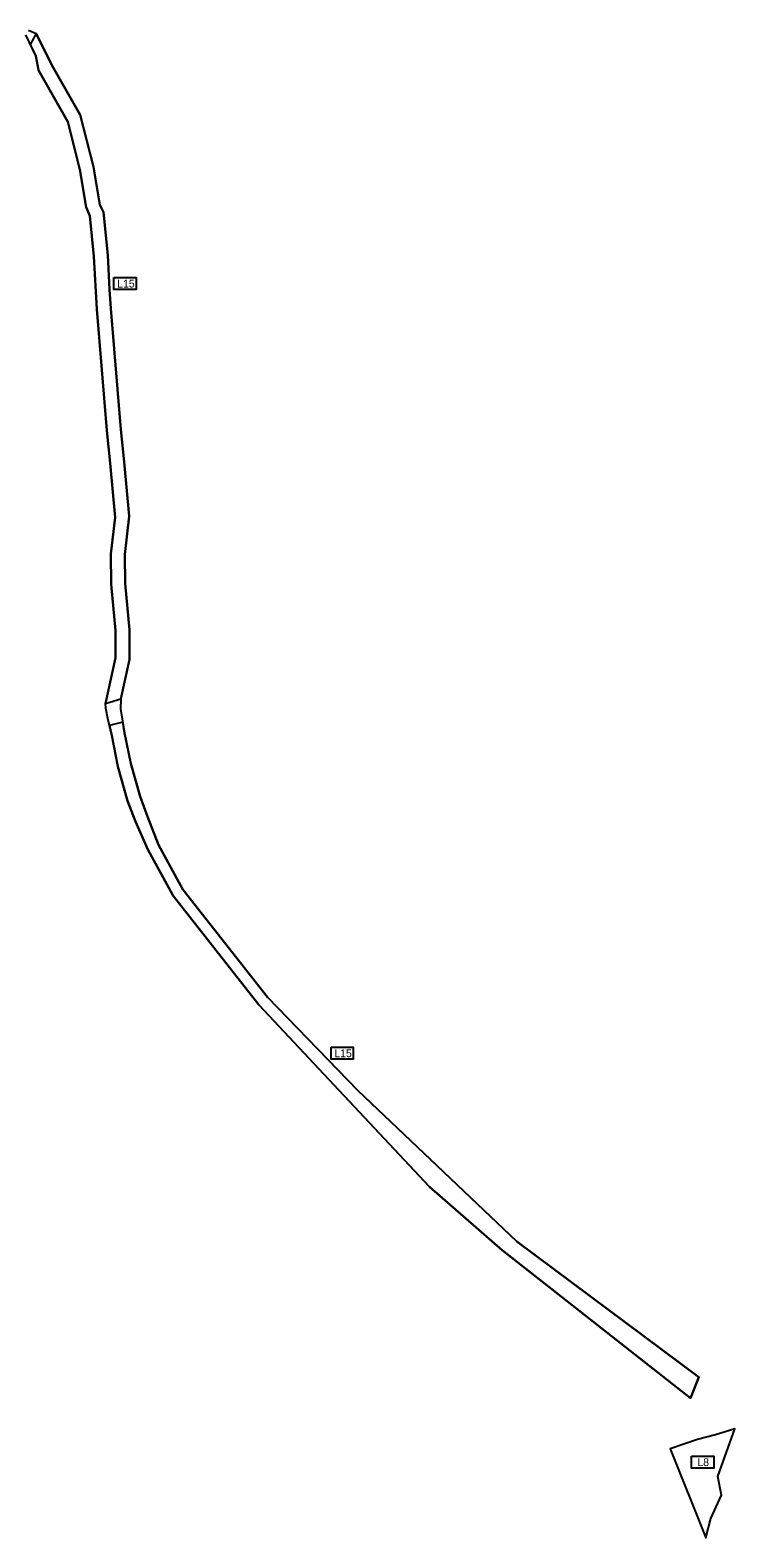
# Model space of a CAD drawing. Extents: x -547623 to -530360, y -1095798 to -1086523.
# Drawn here: x -541905 to -541000, y -1093739 to -1091805 of the extents above; entities that cross this region are included whole.
import ezdxf

# ---------------------------------------------------------------- set-up
doc = ezdxf.new("R2010")
doc.units = 0
for name, color, linetype in [('Vrstva 32', 7, 'Continuous'), ('Vrstva 33', 7, 'Continuous'), ('Vrstva 36', 7, 'Continuous'), ('Vrstva 73', 7, 'Continuous')]:
    doc.layers.add(name, color=color, linetype=linetype)

msp = doc.modelspace()

# ---------------------------------------------------------------- linework, layer by layer
at = {"layer": 'Vrstva 32'}
msp.add_lwpolyline([(-541024.7, -1093607.4), (-541048.2, -1093613.1), (-541082.9, -1093625.4), (-541037.5, -1093739.4), (-541031.1, -1093714.8), (-541017, -1093684.6), (-541022.1, -1093660.8), (-541000.1, -1093599.5), (-541024.7, -1093607.4)], dxfattribs=at)
at = {"layer": 'Vrstva 33'}
msp.add_lwpolyline([(-541906.8, -1091804.9), (-541896.8, -1091809.2), (-541876.6, -1091850), (-541840.6, -1091913.6), (-541823.3, -1091980.1), (-541815.1, -1092029.1), (-541810.4, -1092038.5), (-541805.1, -1092093.6), (-541802.6, -1092137.8), (-541801.1, -1092162.1), (-541788.1, -1092317.1), (-541783.9, -1092358.6), (-541777.5, -1092428.5), (-541782.9, -1092477.8), (-541782.7, -1092514.7), (-541776.9, -1092574.5), (-541776.9, -1092577.3), (-541777, -1092593.1), (-541777.2, -1092612.3), (-541788.1, -1092663), (-541788.7, -1092676.1), (-541783.3, -1092706.6), (-541775.4, -1092745.9), (-541763.4, -1092788.4), (-541753.9, -1092814), (-541739.8, -1092850.1), (-541708.5, -1092907.4), (-541599.8, -1093045.5), (-541484.2, -1093165.6), (-541279.8, -1093359), (-541046.4, -1093533.4), (-541057.1, -1093560.2), (-541298.9, -1093370.5), (-541392.1, -1093289), (-541611.1, -1093055.4), (-541720.8, -1092916), (-541721.5, -1092914.9), (-541753.6, -1092856.2), (-541769.6, -1092820.4), (-541779.5, -1092793.6), (-541791.9, -1092749.8), (-541799.9, -1092710), (-541805, -1092688.3), (-541807.6, -1092674.9), (-541807.7, -1092668.9), (-541795.2, -1092610.4), (-541795, -1092593), (-541794.9, -1092577.1), (-541794.9, -1092575.3), (-541800.7, -1092515.6), (-541800.9, -1092476.8), (-541795.4, -1092430.1), (-541801.8, -1092360.4), (-541806.1, -1092318.7), (-541819.1, -1092163.1), (-541823, -1092095.3), (-541828.1, -1092043.1), (-541832.8, -1092032.1), (-541840.9, -1091983.8), (-541856.3, -1091922.4), (-541893.7, -1091856.4), (-541897.5, -1091838), (-541910.2, -1091811)], dxfattribs=at)
at = {"layer": 'Vrstva 36'}
for points in [[(-541797.2, -1092122.3), (-541768.5, -1092122.3), (-541768.5, -1092137.8), (-541797.2, -1092137.8)], [(-541518.4, -1093109.9), (-541489.8, -1093109.9), (-541489.8, -1093125.4), (-541518.4, -1093125.4)], [(-541055.6, -1093634.6), (-541026.9, -1093634.6), (-541026.9, -1093650.1), (-541055.6, -1093650.1)]]:
    msp.add_lwpolyline(points, close=True, dxfattribs=at)
at = {"layer": 'Vrstva 73'}
for points in [[(-541899.9, -1091814.9), (-541904.5, -1091823.2), (-541897.5, -1091838), (-541893.7, -1091856.4), (-541856.3, -1091922.4), (-541840.9, -1091983.8), (-541832.8, -1092032.1), (-541828.1, -1092043.1), (-541823, -1092095.3), (-541819.1, -1092163.1), (-541806.1, -1092318.7), (-541801.8, -1092360.4), (-541795.4, -1092430.1), (-541800.9, -1092476.8), (-541800.7, -1092515.6), (-541794.9, -1092575.3), (-541794.9, -1092577.1), (-541795, -1092593), (-541795.2, -1092610.4), (-541807.7, -1092668.9), (-541802.3, -1092667), (-541788.1, -1092663), (-541777.2, -1092612.3), (-541777, -1092593.1), (-541776.9, -1092577.3), (-541776.9, -1092574.5), (-541782.7, -1092514.7), (-541782.9, -1092477.8), (-541777.5, -1092428.5), (-541783.9, -1092358.6), (-541788.1, -1092317.1), (-541801.1, -1092162.1), (-541802.6, -1092137.8), (-541805.1, -1092093.6), (-541810.4, -1092038.5), (-541815.1, -1092029.1), (-541823.3, -1091980.1), (-541840.6, -1091913.6), (-541876.6, -1091850), (-541896.8, -1091809.2), (-541899, -1091813.2), (-541899.9, -1091814.9)], [(-541802.9, -1092697.2), (-541799.9, -1092710), (-541791.9, -1092749.8), (-541779.5, -1092793.6), (-541769.6, -1092820.4), (-541753.6, -1092856.2), (-541721.5, -1092914.9), (-541720.8, -1092916), (-541611.1, -1093055.4), (-541392.1, -1093289), (-541298.9, -1093370.5), (-541057.1, -1093560.2), (-541046.4, -1093533.4), (-541279.8, -1093359), (-541484.2, -1093165.6), (-541599.8, -1093045.5), (-541708.5, -1092907.4), (-541739.8, -1092850.1), (-541753.9, -1092814), (-541763.4, -1092788.4), (-541775.4, -1092745.9), (-541783.3, -1092706.6), (-541785.7, -1092692.7), (-541802.9, -1092697.2)], [(-541024.7, -1093607.4), (-541048.2, -1093613.1), (-541082.9, -1093625.4), (-541037.5, -1093739.4), (-541031.1, -1093714.8), (-541017, -1093684.6), (-541022.1, -1093660.8), (-541000.1, -1093599.5), (-541024.7, -1093607.4)]]:
    msp.add_lwpolyline(points, dxfattribs=at)

# ---------------------------------------------------------------- texts
at = {"layer": 'Vrstva 36'}
for s, p in [('L15', (-541792.8, -1092135.1)), ('L15', (-541514.1, -1093122.7)), ('L8', (-541048.1, -1093647.4))]:
    msp.add_text(s, height=10, dxfattribs=at).set_placement(p)

doc.saveas('drawing.dxf')
